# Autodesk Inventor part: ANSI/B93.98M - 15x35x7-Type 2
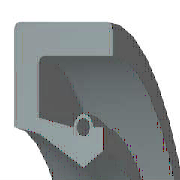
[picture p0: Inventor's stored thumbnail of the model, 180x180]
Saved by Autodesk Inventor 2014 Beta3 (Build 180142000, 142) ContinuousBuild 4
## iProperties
IsCustomPart: 0
Created: 2010-02
Part Number: ANSI/B93.98M - 15x35x7-Type 2
Material: Rubber
Description: Rotary shaft lip type seals 2 - Metal cased
Document SubType Name: Modeling
Standard: ANSI/B93.98M
Designer: Thom Tremblay
Standards Organization: ANSI
Language: en-US
Size Designation: 15x35x7-Type 2
Categories: <MemberInstance><Categories><Category DisplayName="Shaft Parts" InternalName="7f7aeb1f-a693-4053-b835-cee3144e0d98" Mnemonic="SHFT"><Category DisplayName="Seali
Density: 0.93 g/cm^3
Appearance: Rubber - Black - Version 1.1
Author: Thom Tremblay
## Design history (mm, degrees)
node "WorkPlane2"
node "Sketch1"
node "WorkPoint1"
node "WorkPlane3"
fillet "Fillet1" dims "d38" = 0.4 (= 0.05 x b)
body "Solid1"
revolve "Revolution1" stored, may be unused: angle "d37" = 360 deg
sketch "Sketch2"
  geometry: L1 (15.5, -0.4)-(16.7, -0.4); L2 (15.5, 0)-(15.5, -0.4); L3 (17.5, 0)-(15.5, 0); L4 (17.5, -8)-(17.5, 0); L5 (10.46, -8)-(17.5, -8); L6 (9.21, -4.8)-(10.46, -8); L7 (8.301, -4.251)-(9.21, -4.8); L8 (7.5, -2.2)-(8.301, -4.251); L9 (8.553, -1.2)-(7.5, -2.2); L10 (11.053, -1.2)-(8.553, -1.2); L11 (11.053, -2.2)-(11.053, -1.2); L12 (11.053, -6.4)-(11.053, -3.8); L13 (12.386, -6.4)-(11.053, -6.4); L14 (12.386, -7.2)-(12.386, -6.4); L15 (16.7, -7.2)-(12.386, -7.2); L16 (16.7, -0.4)-(16.7, -7.2); L17 (0, -15.959)-(0, 2.029); L18 (0, -15.959)-(0, 2.029); L19 (0, -19.557)-(0, 5.626) reference; L20 (-5.2, 0)-(31.2, 0) reference; A1 r 0.8 centre (11.053, -3) between (11.053, -3.8) and (11.053, -2.2)
  constraints: 36 end point, 7 vertical, 6 horizontal, 2 collinear, 2 point on circle, 1 centre point, 1 parallel, 1 point on line
  dimensions: "d2" = 0.4 distance of L2.start L1.start (= 0.05 x b); "d4" = 8 distance of L4.start L3.start (= b); "d6" = 0.8 horizontal distance of L1.end L3.start (= 0.1 x b); "d8" = 0.8 horizontal distance of L15.start L4.start (= 0.1 x b); "d10" = 0.8 distance of L14.start L13.start (= 0.1 x b); "d12" = 0.8 vertical distance of L1.end L10.start (= 0.1 x b); "d14" = 1 distance of L11.start L10.start (= 0.125 x b); "d16" = 0.8 radius of A1 (= 0.1 x b); "d18" = 0 horizontal distance of A1.centre L12.end; "d20" = 1 vertical distance of L9.start L8.start (= 0.125 x b); "d22" = 2.05128 vertical distance of L8.start L7.start (= 0.25641 x b); "d24" = 3.2 vertical distance of L6.start L5.start (= 0.4 x b); "d26" = 2 distance of L3.start L2.start (= 0.1 x dd - 0.1 x Diam); "d28" = 1.05263 horizontal distance of L9.start L8.start (= 0.0526316 x dd - 0.0526316 x Diam); "d30" = 2.5 distance of L10.start L9.start (= 0.125 x dd - 0.125 x Diam); "d32" = 1.33333 distance of L13.start L12.start (= 0.0666667 x dd - 0.0666667 x Diam); "d34" = 1.25 horizontal distance of L6.start L5.start (= 0.0625 x dd - 0.0625 x Diam); "d36" = 0.90909 horizontal distance of L7.start L6.start (= 0.0454545 x dd - 0.0454545 x Diam); "msp_d39" = 15 diameter of L8.start L17 (= Diam); "msp_d40" = 35 diameter of L4 L17 (= dd)
other parameters: "dd" = 35 [user parameter; used in 7 equation terms], "Diam" = 15 [user parameter; used in 7 equation terms], "b" = 8 [user parameter; used in 13 equation terms], "d0" = -8 (computed from b), "d1" = 0.4 (derived), "d3" = 8 (derived), "d5" = 0.8 (derived), "d7" = 0.8 (derived), "d9" = 0.8 (derived), "d11" = 0.8 (derived), "d13" = 1 (derived), "d15" = 0.8 (derived), "d17" = 0 (derived), "d19" = 1 (derived), "d21" = 2.05128 (derived), "d23" = 3.2 (derived), "d25" = 2 (derived), "d27" = 1.05263 (derived), "d29" = 2.5 (derived), "d31" = 1.33333 (derived), "d33" = 1.25 (derived), "d35" = 0.90909 (derived), "d42" = 0
